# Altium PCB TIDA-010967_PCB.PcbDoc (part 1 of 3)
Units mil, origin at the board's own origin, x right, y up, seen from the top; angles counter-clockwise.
Board outline 2322.7 x 960 mil, 2 copper layers (Top Layer, Bottom Layer), stack 44.731 mil thick; 178 components, 80 nets, 496 pads, 399 vias.
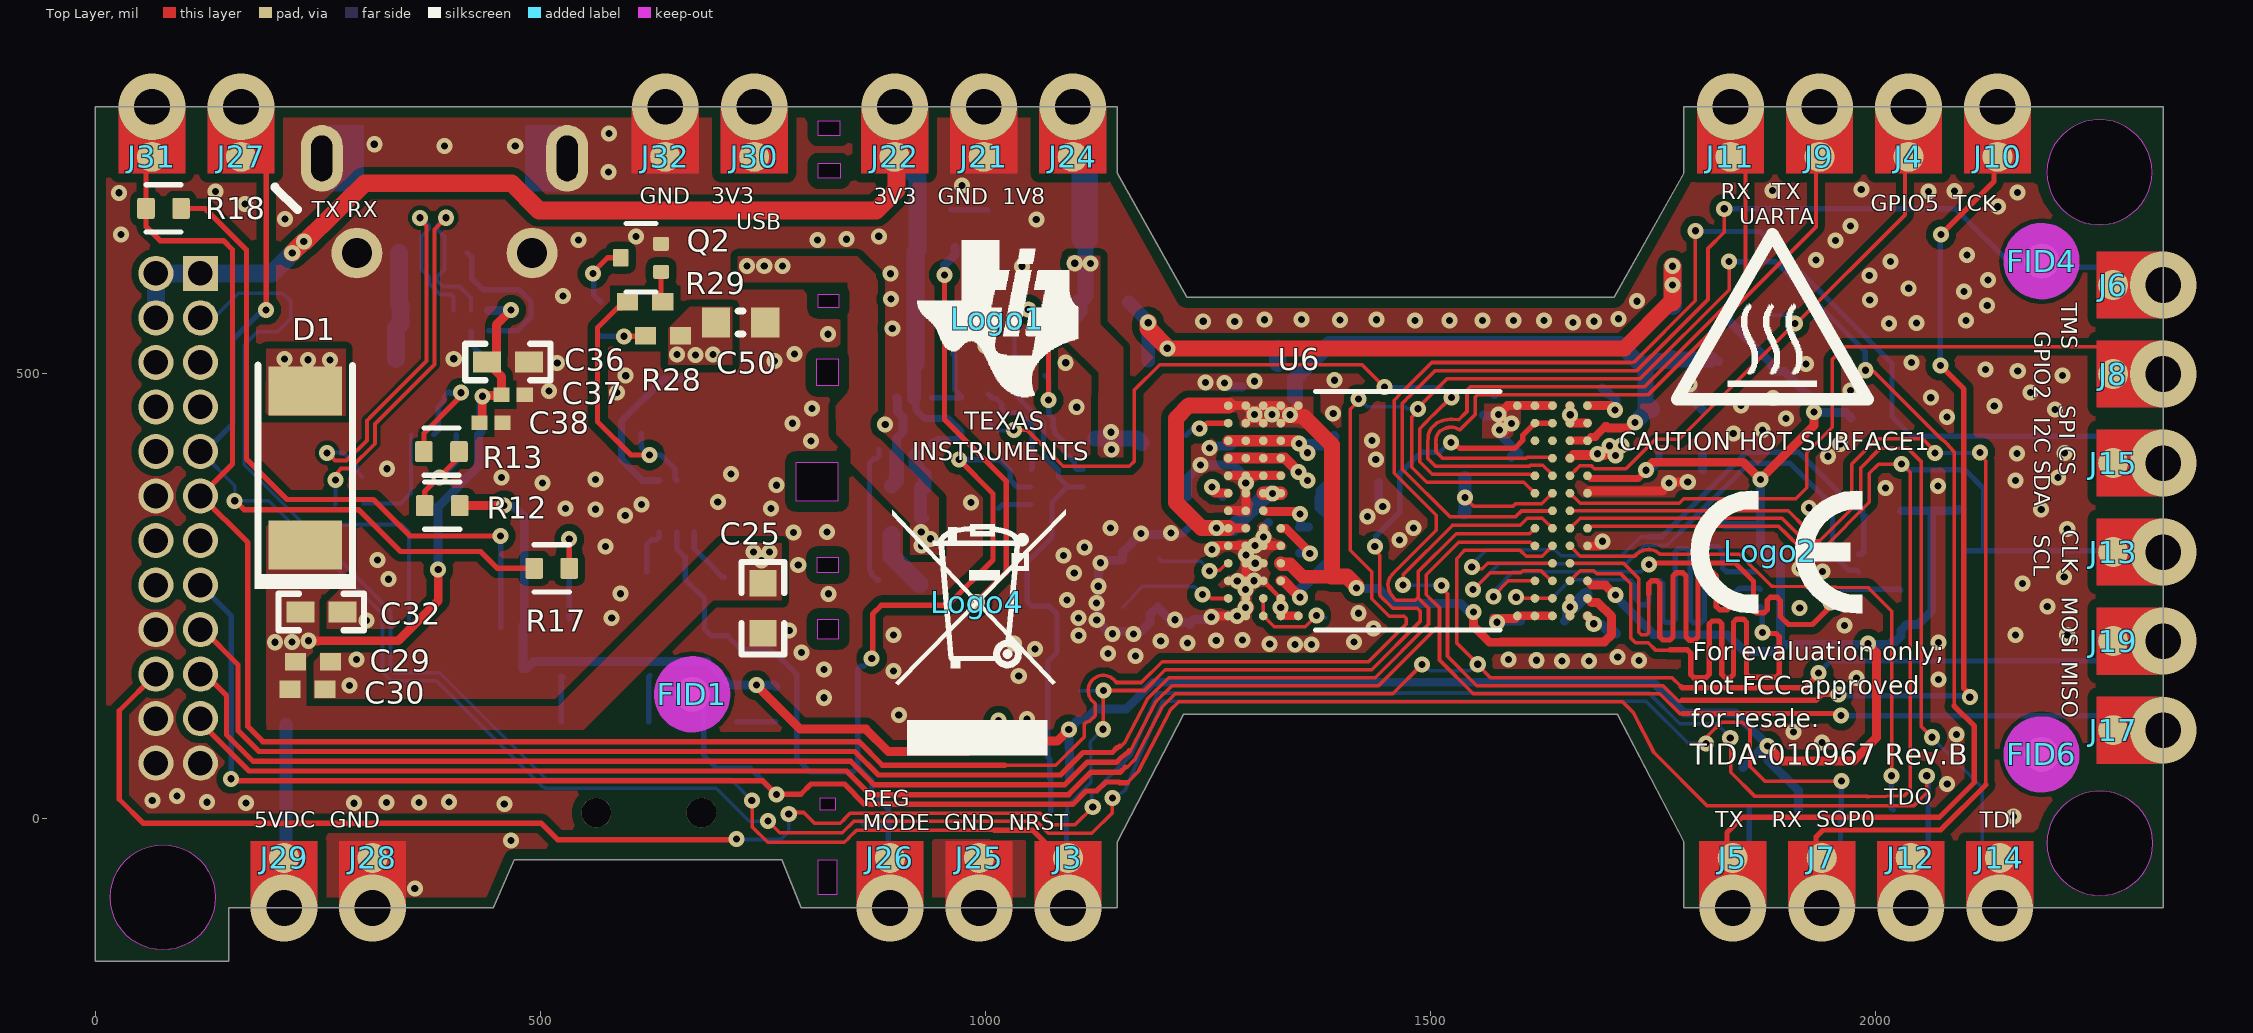
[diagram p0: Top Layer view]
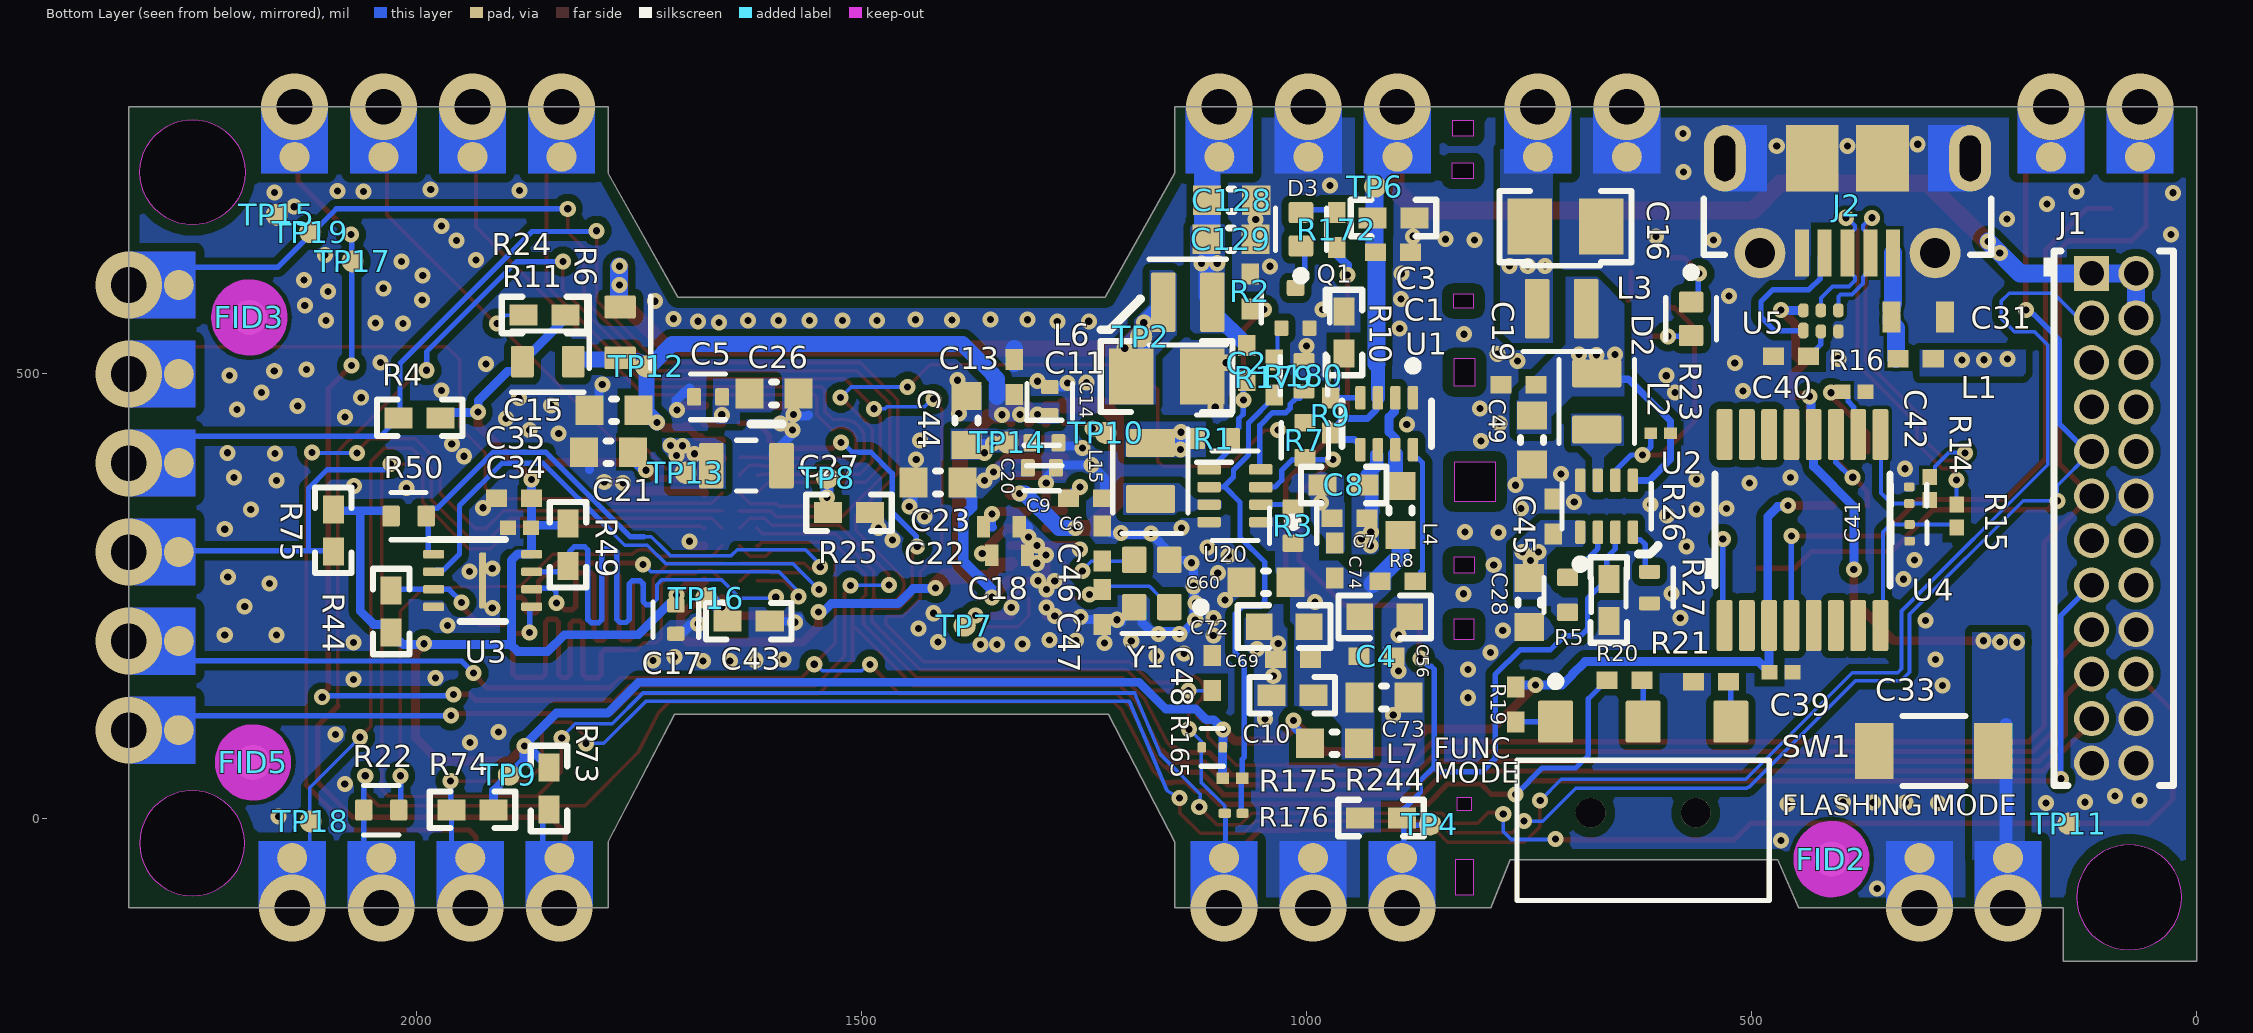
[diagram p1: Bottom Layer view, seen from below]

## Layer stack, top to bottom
Top Solder: solder mask 0.4, Solder Resist, Dk 4.5
Top Layer: signal copper 1.401
Dielectric 1: core 41.929, FR-4 High Tg135 (KB-6164), Dk 4.5
Bottom Layer: signal copper 1.401
Bottom Solder: solder mask 0.4, Solder Resist, Dk 4.5

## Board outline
150,-160 150,-100 447,-100 470.42,-45.84 470.38,-45.81 771.2,-45.81 770.94,-45.67 793,-100 1147.72,-100 1147.72,-25.77 1222.67,117.74 1709.51,117.74 1784.42,-25.77 1784.42,-100 2322.7,-100 2322.7,800 1784.42,800 1784.42,725.77 1705.96,586 1225.82,586 1147.73,725.77 1147.73,800 0,800 0,-160
cut-out: 2192.07,726.38 ccw(c2251.12,726.38) 2251.12,667.32 ccw(c2251.12,726.38) 2310.18,726.38 ccw(c2251.12,726.38) 2251.12,785.43 ccw(c2251.12,726.38)
cut-out: 75.87,-147.12 cw(c75.87,-88.07) 16.81,-88.07 cw(c75.87,-88.07) 75.87,-29.01 cw(c75.87,-88.07) 134.92,-88.07 cw(c75.87,-88.07)
cut-out: 2192.49,-27.28 cw(c2251.54,-27.28) 2251.54,31.77 cw(c2251.54,-27.28) 2310.6,-27.28 cw(c2251.54,-27.28) 2251.54,-86.34 cw(c2251.54,-27.28)
cut-out: 787.23,357.01 787.23,400.93 834.15,400.93 834.15,357.01
cut-out: 811.61,202.06 811.61,224.32 834.73,224.32 834.73,202.06
cut-out: 810.96,276.6 810.96,294.06 834.49,294.06 834.49,276.6
cut-out: 812.12,719.77 812.12,736.24 836.79,736.24 836.79,719.77
cut-out: 811.87,574.08 811.87,589.42 835.26,589.42 835.26,574.08
cut-out: 812.12,767.55 812.12,784.24 836.23,784.24 836.23,767.55
cut-out: 810.45,486.64 810.45,516.86 834.73,516.86 834.73,486.64
cut-out: 814.29,9.7 814.29,23.97 830.94,23.97 830.94,9.7
cut-out: 812.08,-85.22 812.08,-45.84 833,-45.84 833,-85.22

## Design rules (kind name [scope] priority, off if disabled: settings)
AcuteAngle [All] p1 off: minimum=4.50000000000000E+0001 checktracksonly=FALSE
AssemblyTestPointUsage [All] p1: valid=2
BoardOutlineClearance [All] p1: gap=12 ignorepadtopadclearanceinfootprint=FALSE
Clearance Clearance_Keepout [IsKeepOut] p1: gap=5 ignorepadtopadclearanceinfootprint=TRUE
Clearance "Clearance_TX and RX" [InNetClass('TX and RX')] p2: gap=8 ignorepadtopadclearanceinfootprint=FALSE except(0: Text-Hole; 4: Arc-Text Track-Text SMDPad-Text THPad-Text Via-Text Fill-Text Poly-Text Region-Text Text-Text; 5.3: Arc-Via Arc-Fill Arc-Poly Arc-Region Track-Via Track-Fill Track-Poly Track-Region Poly-Region; 6: Arc-Hole Track-Hole SMDPad-Via SMDPad-Hole THPad-Hole Via-Hole; 7.7: Fill-Fill Fill-Poly Fill-Region Poly-Poly Region-Region; 10: Arc-SMDPad Arc-THPad Track-SMDPad Track-THPad SMDPad-SMDPad SMDPad-THPad THPad-THPad THPad-Via; 11: Fill-Hole Poly-Hole Region-Hole)
Clearance Clearance_BGA [WithinRoom('BGA1')] p3: gap=4 ignorepadtopadclearanceinfootprint=FALSE except(8: Fill-Fill Fill-Poly Fill-Region Poly-Poly Poly-Region Region-Region; 10: Fill-Hole Poly-Hole Region-Hole)
Clearance Clearance_USB [WithinRoom('USB')] p4: gap=4 ignorepadtopadclearanceinfootprint=FALSE except(8: Fill-Fill Fill-Poly Fill-Region Poly-Poly Poly-Region Region-Region; 10: Fill-Hole Poly-Hole Region-Hole)
Clearance "top and bottom" [OnTopLayer or OnBottomLayer] p5: gap=6 ignorepadtopadclearanceinfootprint=TRUE except(5: Arc-Arc Arc-Track Arc-SMDPad Arc-Hole Track-Track Track-SMDPad Track-Hole SMDPad-Hole THPad-Hole Via-Hole Text-Hole; 5.1: SMDPad-SMDPad; 7: Arc-Fill Arc-Poly Arc-Region Track-Fill Track-Region; 8: Track-Poly SMDPad-Fill SMDPad-Poly SMDPad-Region THPad-Fill THPad-Poly THPad-Region Via-Fill Via-Poly Via-Region Poly-Poly; 10: Fill-Fill Fill-Poly Fill-Region Poly-Region Region-Region; 11: Fill-Hole Poly-Hole Region-Hole)
Clearance Clearance_KO-J5 [IsKeepOut and IsTrack vs InComponent('J5')] p6: gap=19.6 ignorepadtopadclearanceinfootprint=FALSE
Clearance [All] p7: gap=6 ignorepadtopadclearanceinfootprint=TRUE except(0: Text-Hole; 5: Arc-Arc Arc-Track Arc-SMDPad Track-Track Track-SMDPad; 5.1: SMDPad-SMDPad; 7: Arc-Fill Arc-Poly Arc-Region Track-Fill Track-Region; 8: SMDPad-Fill SMDPad-Poly SMDPad-Region THPad-Fill THPad-Poly THPad-Region; 10: Fill-Fill Fill-Poly Fill-Region Poly-Region Region-Region; 11: Fill-Hole Poly-Hole Region-Hole; 12: Track-Poly; 15: Poly-Poly)
Clearance Same_net [All] p8: gap=0 ignorepadtopadclearanceinfootprint=TRUE
ComponentClearance ComponentClearance_MatingCon-3D [All vs not InAnyComponent] p1: gap=0 collisioncheckmode=3 verticalgap=0 showdistances=FALSE
ComponentClearance "ComponentClearance_WEE Logo" [InComponent('Logo4')] p2: gap=0 collisioncheckmode=3 verticalgap=0 showdistances=TRUE
ComponentClearance ComponentClearance_R77 [InComponent('R77') vs InComponent('Logo1')] p3: gap=0 collisioncheckmode=3 verticalgap=0 showdistances=TRUE
ComponentClearance ComponentClearance_Logo [InComponentClass('Logo')] p4: gap=0 collisioncheckmode=3 verticalgap=0 showdistances=TRUE
ComponentClearance "ComponentClearance_Mounting Holes_Fiducial Marks" [InComponentClass('FiducialMark') vs InPadClass('Mounting Holes PADS')] p5: gap=50 collisioncheckmode=3 verticalgap=10 showdistances=TRUE
ComponentClearance [All] p6: gap=6 collisioncheckmode=3 verticalgap=10 showdistances=TRUE
DiffPairsRouting 90ohm [All] p1: maxlimit=4.5 minlimit=4.5 mostfreqgap=4.5 toplayer_minwidth=4.5 toplayer_maxwidth=4.5 toplayer_prefwidth=4.5 bottomlayer_minwidth=4.5 bottomlayer_maxwidth=4.5 bottomlayer_prefwidth=4.5 maxuncoupledlength=500
FabricationTestPointUsage TestPointUsage [All] p1: valid=2 allowmultiple=FALSE
FabricationTestpoint Testpoint [All] p1: side=3 testpointundercomponent=TRUE minsize=40 maxsize=100 preferedsize=60 minholesize=0 maxholesize=40 preferedholesize=32 testpointgrid=1 allowsidetop=TRUE allowsidebottom=TRUE usegrid=TRUE gridtolerance=0.01
FanoutControl Fanout_LCC [IsLCC] p1: bgadir=Out bgaviamode=Centered fanoutstyle=Auto fanoutdirection=Alternating viagrid=1 // Fanout_LCC (Default Rule)
FanoutControl Fanout_BGA [IsBGA] p2: bgadir=Out bgaviamode=Centered fanoutstyle=Auto fanoutdirection=Alternating viagrid=1 // Fanout_BGA (Default Rule)
FanoutControl Fanout_Default [All] p4: bgadir=Out bgaviamode=Centered fanoutstyle=Auto fanoutdirection=Alternating viagrid=1 // Fanout_Default (Default Rule)
FanoutControl Fanout_Small [(CompPinCount < 5)] p5: bgadir=Out bgaviamode=Centered fanoutstyle=Auto fanoutdirection=OutThenIn viagrid=1 // Fanout_Small (Default Rule)
Height Room_Hieght [WithinRoom('Room_Hieght 1 MM')] p1: minheight=0 maxheight=41.34 prefheight=39.37
HoleSize [All] p1: absolutevalues=TRUE maxlimit=280 minlimit=5.9 maxpercent=80.000 minpercent=20.000
HoleToHoleClearance HoleToHoleClearance_1 [WithinRoom('BGA1')] p1: gap=4 allowstackedmicrovias=FALSE
MatchedLengths MatchLengths_xSignals_U3_U6 [InxSignalClass('xSignals_U3_U6_MatchLengthsClass')] p1: tolerance=30 checknetsindiffpair=FALSE checkdiffpairvsdiffpair=TRUE checkxsignals=TRUE checkothers=TRUE
MatchedLengths MatchLengths_xSignals_U2_U1_1 [InxSignalClass('xSignals_U2_U1_MatchLengthsClass_1')] p2: tolerance=100 checknetsindiffpair=FALSE checkdiffpairvsdiffpair=TRUE checkxsignals=TRUE checkothers=TRUE
MatchedLengths MatchLengths_U2_Passives_U1 [InxSignalClass('xSignals_U2_Passives_U1_MatchLengthsClass')] p3: tolerance=100 checknetsindiffpair=FALSE checkdiffpairvsdiffpair=TRUE checkxsignals=TRUE checkothers=TRUE
MatchedLengths MatchLengths_xSignals_U2_Passives [InxSignalClass('xSignals_U2_Passives_MatchLengthsClass')] p4: tolerance=100 checknetsindiffpair=FALSE checkdiffpairvsdiffpair=TRUE checkxsignals=TRUE checkothers=TRUE
MatchedLengths MatchLengths_xSignals_U2_U1 [InxSignalClass('xSignals_U2_U1_MatchLengthsClass')] p5: tolerance=100 checknetsindiffpair=FALSE checkdiffpairvsdiffpair=TRUE checkxsignals=TRUE checkothers=TRUE
MatchedLengths [InxSignalClass('QPSI')] p6: tolerance=10 checknetsindiffpair=FALSE checkdiffpairvsdiffpair=TRUE checkxsignals=TRUE checkothers=TRUE
MinimumAnnularRing MinimumAnnularRing_ThermalPadVias [IsVia and InAnyComponent] p1: minimumring=3.9
MinimumAnnularRing [All] p2: minimumring=3.9
MinimumSolderMaskSliver MinimumSolderMaskSliver_Logo [InComponentClass('Logo') vs InComponentClass('Logo')] p1: minsoldermaskwidth=0.7
MinimumSolderMaskSliver [All] p2: minsoldermaskwidth=3.5
PlaneConnect [All] p1: planeconnectstyle=Relief reliefexpansion=10 reliefentries=4 reliefconductorwidth=10 reliefairgap=10
PolygonConnect [All] p1: connectstyle=Direct reliefconductorwidth=10 reliefentries=4 polygonreliefangle="90 Angle" airgapwidth=10
RoomDefinition BGA1 [InComponentClass('Components Class 2')] p1: confinementstyle=ConfineIn formatcopy=TRUE lockcomponents=FALSE outline 1572.65,427.73 1907.13,427.73 1907.13,252.98 1572.65,252.98
RoomDefinition USB [InComponentClass('Components Class 2')] p2: confinementstyle=ConfineIn formatcopy=TRUE lockcomponents=FALSE outline 252.62,689.5 405.92,689.5 405.92,368.59 252.62,368.59
RoutingVias ThermalPadVias [IsVia and InAnyComponent] p1: holewidth=7.87 width=19.68 viastyle="Through Hole" minholewidth=5 minwidth=13 maxholewidth=12.99 maxwidth=23.62
RoutingVias [All] p2: holewidth=12.2 width=22.4 viastyle="Through Hole" minholewidth=5.9 minwidth=14 maxholewidth=20 maxwidth=40
SMDToCorner [All] p1: distance=25000
SilkToBoardRegionClearance [Not ((IsComment or IsDesignator) And (Hide <> 'False')) and not InRegion(1000,500,4000,800)] p1:
SilkToSilkClearance [All] p1: silktosilkclearance=3
SilkToSolderMaskClearance SilkToSolderMaskClearance_OutLine [istrack and InAnyComponent] p1: minsilkscreentomaskgap=0 clearancetoexposedcopper=FALSE
SilkToSolderMaskClearance SilkscreenOverComponentPads [IsPad] p2: minsilkscreentomaskgap=3 clearancetoexposedcopper=FALSE
SolderMaskExpansion [All] p1: expansion=0 istentingtop=FALSE
SupplyNets "Schematic Supply Nets_18" [InNet('RADAR_1V_RF_OUT')] p1: voltage=0.000
SupplyNets "Schematic Supply Nets_17" [InNet('5V_IN_USB')] p2: voltage=0.000
SupplyNets "Schematic Supply Nets_16" [InNet('OUT_3V3')] p3: voltage=0.000
SupplyNets "Schematic Supply Nets_15" [InNet('REG_OUT_1V8')] p4: voltage=0.000
SupplyNets "Schematic Supply Nets_14" [InNet('REG_3V3')] p5: voltage=0.000
SupplyNets "Schematic Supply Nets_13" [InNet('RADAR_1V4_APLL')] p6: voltage=0.000
SupplyNets "Schematic Supply Nets_12" [InNet('RADAR_SRAM_1V2')] p7: voltage=0.000
SupplyNets "Schematic Supply Nets_11" [InNet('GND')] p8: voltage=0.000
SupplyNets "Schematic Supply Nets_10" [InNet('RADAR_1V2')] p9: voltage=0.000
SupplyNets "Schematic Supply Nets_9" [InNet('RADAR_1P2_RF')] p10: voltage=0.000
SupplyNets "Schematic Supply Nets_8" [InNet('RADAR_1V8')] p11: voltage=0.000
SupplyNets "Schematic Supply Nets_7" [InNet('RADAR_1V4_SYNTH')] p12: voltage=0.000
SupplyNets "Schematic Supply Nets_6" [InNet('USB_5V')] p13: voltage=0.000
SupplyNets "Schematic Supply Nets_5" [InNet('USB_INPUT_3V3')] p14: voltage=0.000
SupplyNets "Schematic Supply Nets_4" [InNet('RADAR_3V3')] p15: voltage=0.000
SupplyNets "Schematic Supply Nets_3" [InNet('REG_1V8')] p16: voltage=0.000
SupplyNets "Schematic Supply Nets_2" [InNet('VPP_1P7')] p17: voltage=0.000
SupplyNets "Schematic Supply Nets_1" [InNet('RADAR_VBGAP')] p18: voltage=0.000
SupplyNets "Schematic Supply Nets" [InNet('DC_OUT_3V3')] p19: voltage=0.000
UnRoutedNet [All] p1: checkbadconnections=TRUE
Width [All] p1: maxlimit=100 minlimit=4 preferedwidth=10 toplayer_prefwidth=6 minimp=50.000000 maximp=50.000000 favimp=50.000000
12 further rules are at their usual default settings.

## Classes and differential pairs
component class TIDA-010967_xWRL6432_Chip: C43 C46 C47 C48 R4 R22 R24 R25 R73 R74 R75 R165 TP7 TP8 TP10 TP12 TP13 TP14 TP15 TP16 TP17 TP18 TP19 U6 Y1
component class TIDA-010967_USB_PWR_Connector: C29 C30 C31 C32 C33 C36 C37 C38 C39 C40 C41 C42 D1 J1 J2 J3 J4 J5 J6 J7 J8 J9 J10 J11 J12 J13 J14 J15 J17 J19 J21 J22 J24 J25 J26 J27 J28 J29 J30 J31 J32 J? L1 R12 R13 R14 R15 R16 R17 R18 R19 R20 R21 SW1 U4 U5
component class TIDA-010967_QSPI_Flash: C34 C35 R44 R49 R50 U3
component class TIDA-010967_Decoupling_caps: C5 C6 C9 C13 C14 C15 C17 C18 C20 C21 C22 C23 C26 C27 C44 L7 R6 R11
component class TIDA-010967_DC_Regulators: C1 C2 C3 C4 C7 C8 C10 C11 C16 C19 C25 C28 C45 C49 C50 C56 C60 C69 C72 C73 C74 C128 C129 D2 D3 L2 L3 L4 L6 L15 Q1 Q2 R1 R2 R3 R5 R7 R8 R9 R10 R23 R26 R27 R28 R29 R172 R175 R176 R179 R180 R244 TP2 TP4 TP6 TP9 TP11 U1 U2 U20
net class POWER: PMIC_CLKOUT_SOP1 REG_1V8 REG_OUT_1V8
net class Regions: GND XTALP
component class Logo: Logo1
component class FiducialMark: FID1 FID2 FID3 FID4 FID5 FID6
component class TIDA-010967_Hardware: "CAUTION HOT SURFACE1" FID1 FID2 FID3 FID4 FID5 FID6 Logo1 Logo2 Logo4 ZZ1 ZZ2 ZZ3 ZZ4 ZZ5
component class AssemblyNote: ZZ1 ZZ2 ZZ3 ZZ4 ZZ5
component class Header: J1 LD2 LD4 SW2
differential pair USB_DifferentialPair1: +USB_DP -USB_DM
differential pair CAN: +"" -""
differential pair LVDS_FRCLK: +"" -""
differential pair LVDS_FRCLK_DP8: +"" -""
differential pair LVDS_CLK: +"" -""
differential pair LVDS_CLK_DP7: +"" -""
differential pair LVDS_3: +"" -""
differential pair LVDS_3_DP6: +"" -""
differential pair LVDS_2: +"" -""
differential pair LVDS_2_DP5: +"" -""
differential pair LVDS_1: +"" -""
differential pair LVDS_1_DP4: +"" -""
differential pair LVDS_0: +"" -""
differential pair LVDS_0_DP3: +"" -""
differential pair USB_DP1: +USBDP -USBDM

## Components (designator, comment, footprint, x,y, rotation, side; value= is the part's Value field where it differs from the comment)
C1 "GRT155C81A105KE01D" 0402L 902.62,636.34 r180 bottom value=1uF
C2 "GRM1555C1H100JA01D" 0402L 1066.97,512.13 r270 bottom value=10pF
C3 "GCM155R71H104KE02D" 0402 902.23,675.03 r180 bottom value=0.1uF
C4 "GRT155C81A105KE01D" 0402L 921.46,182.75 r180 bottom value=1uF
C5 "GRM155R61A225ME01D" FP-GRM155R61A225ME01D_0402-MFG 1672.07,474.04 r180 bottom value=2.2µF
C6 "C1005X7R1H473K050BB" 0402L 1247.52,360.04 r180 bottom value=0.047uF
C7 "GRT155C81A105KE01D" 0402L 951.51,337.76 r0 bottom value=1uF
C8 "GCM155R71H104KE02D" 0402 958.13,375.12 r180 bottom value=0.1uF
C9 "GRM155R61A225ME01D" FP-GRM155R61A225ME01D_0402-MFG 1297.18,394.28 r0 bottom value=2.2µF
C10 "GCM155R71H104KE02D" 0402 1015.77,138.92 r0 bottom value=0.1uF
C11 "GRM21BR61A476ME15L" 0805_HV 1156.96,496.95 r180 bottom value=47uF
C13 "GRM155R71C224KA12D" 0402L 1328.14,496.44 r90 bottom value=0.22uF
C14 "GRM155R61A225ME01D" FP-GRM155R61A225ME01D_0402-MFG 1288.21,469.2 r270 bottom value=2.2µF
C15 "GRM188Z71A106MA73D" 0603L 1777.87,459.12 r0 bottom value=10uF
C16 "GRM21BR61A476ME15L" 0805_HV 708.95,665.27 r180 bottom value=47uF
C17 "GRM155R61A225ME01D" FP-GRM155R61A225ME01D_0402-MFG 1708.25,223.76 r90 bottom value=2.2µF
C18 "GRM155R70J105KA12D" 0402S 1333.23,296.06 r180 bottom value=1uF
C19 "GRM1555C1H100JA01D" 0402L 761.79,487.87 r0 bottom value=10pF
C20 "GRM155R61A225ME01D" FP-GRM155R61A225ME01D_0402-MFG 1294.33,422.3 r0 bottom value=2.2µF
C21 "GRM188Z71A106MA73D" 0603L 1783.84,411.93 r0 bottom value=10uF
C22 "GRM155R70J105KA12D" 0402S 1342.73,328.1 r180 bottom value=1uF
C23 "GRM188Z71A106MA73D" 0603L 1414,377.89 r0 bottom value=10uF
C25 "GRM188Z71A106MA73D" 0603_HV 749.85,236.7 r270 top value=10uF
C26 "GRM188Z71A106MA73D" 0603L 1598.21,477.81 r180 bottom value=10uF
C27 "GCJ21BR71C475KA01L" FP-GCJ21BR71C475KA01L_0805-MFG 1628.97,396.86 r0 bottom value=4.7µF
C28 "GRM188R71C474KA88D" 0603L 749.79,243.27 r270 bottom value=0.47uF
C29 "GCM155R71C224KE02D" 0402L 244.49,176.81 r180 top value=0.22uF
C30 "GCM155C71A474KE36D" 0402L 238.1,145.91 r0 top value=0.47uF
C31 "GRT188R61A106KE13D" 0603S 312.8,563.93 r0 bottom value=10uF
C32 "GRM155R61A106ME11D" 0402 253.83,232.53 r180 top value=10uF
C33 "GRM31CR61A476KE15L" 1206_180 295.19,76.51 r0 bottom value=47uF
C34 "GRM033C71A104KE14D" 0201 1883.74,326.93 r180 bottom value=0.1uF
C35 "GRM155R70J105KA12D" 0402L 1890.11,359.96 r0 bottom value=1uF
C36 "0402ZD106MAT2A" 0402_080 463.4,513.17 r0 top value=10uF
C37 "GRM033R61C104KE84D" 0201_033 469.41,476.41 r0 top value=0.1uF
C38 "GRM033R70J103KA01D" 0201 444.44,444.93 r0 top value=0.01uF
C39 "GRM033R61C104KE84D" 0201_033 466.96,164.72 r180 bottom value=0.1uF
C40 "GRM033R61C104KE84D" 0201_033 384.79,479.89 r180 bottom value=0.1uF
C41 "GCM0335C1E220JA16D" FP-GCM0335C1E220JA16D_0201-MFG 322.55,321.38 r90 bottom value=22pF
C42 "GCM0335C1E220JA16D" FP-GCM0335C1E220JA16D_0201-MFG 322.97,363.59 r270 bottom value=22pF
C43 "C1005X7R1H104K050BE" 0402 1626.41,222.13 r180 bottom value=0.1uF
C44 "GRM188Z71A106MA73D" 0603L 1381.93,447.66 r90 bottom value=10uF
C45 "GRM1555C1H471JA01D" 0402L 722.49,339.81 r90 bottom value=470pF
C46 "GJM1555C1H4R7BB01D" 0402L 1229.42,309.15 r270 bottom value=4.7pF
C47 "GJM1555C1H4R7BB01D" 0402L 1229.56,237.9 r90 bottom value=4.7pF
C48 "CL05B224KO5NNNC" 0402L 1105.76,163.78 r270 bottom value=0.22uF
C49 "GRM188Z71A106MA73D" 0603L 746.45,425.59 r270 bottom value=10uF
C50 "GRM188Z71A106MA73D" 0603L 724.93,557.48 r0 top value=10uF
C56 "GRM188Z71A106MA73D" 0603_HV 911.95,227 r180 bottom value=10uF
C60 "GRM188R71C474KA88D" 0603L 1045.37,265.79 r0 bottom value=0.47uF
C69 "GRM1555C1H471JA01D" 0402L 1015.01,179.1 r0 bottom value=470pF
C72 "GRM188Z71A106MA73D" 0603_HV 1025.05,215.91 r0 bottom value=10uF
C73 "GRM188R71C474KA88D" 0603L 912.93,136.47 r180 bottom value=0.47uF
C74 "GRM1555C1H471JA01D" 0402L 968.4,290.29 r90 bottom value=470pF
C128 "GRM188Z71A106MA73D" 0603L 1083.88,695.03 r180 bottom value=10uF
C129 "GRM188Z71A106MA73D" 0603L 1084.82,651.17 r180 bottom value=10uF
"CAUTION HOT SURFACE1" "CAUTION HOT SURFACE" IEC_HotSurface_Small 1883.74,564.43 r0 top
D1 "PMEG3020EP,115" SOD-128 235.78,394.13 r90 top value=30V
D2 "VLMY1500-GS08" FP-VLMY1500-GS08_0402-MFG 567.93,561.74 r270 bottom
D3 "VLMY1500-GS08" FP-VLMY1500-GS08_0402-MFG 1006.08,662.34 r90 bottom
FID1 "Fiducial" Fiducial10-20 670.53,139.97 r0 top
FID2 "Fiducial" Fiducial10-20 410.19,-45.15 r90 bottom
FID3 "Fiducial" Fiducial10-20 2187.29,563.32 r90 bottom
FID4 "Fiducial" Fiducial10-20 2186.11,626.55 r0 top
FID5 "Fiducial" Fiducial10-20 2183.2,63.48 r90 bottom
FID6 "Fiducial" Fiducial10-20 2186.07,72.45 r0 top
J1 "GRPB122VWVN-RC" Sullins_GRPB122VWVN 93.1,337.73 r180 bottom
J2 "105017-0001" CONN_105017-0001 392.23,688.84 r0 bottom
J3 "Castellation 2.54mm" "FP-Castellation 2.54mm_75mills" 1092.59,-100 r90 top
J4 "Castellation 2.54mm" "FP-Castellation 2.54mm_75mills" 2036.65,800 r270 top
J5 "Castellation 2.54mm" "FP-Castellation 2.54mm_75mills" 1839.17,-100 r90 top
J6 "Castellation 2.54mm" "FP-Castellation 2.54mm_75mills" 2322.82,599.73 r180 top
J7 "Castellation 2.54mm" "FP-Castellation 2.54mm_75mills" 1939.17,-100 r90 top
J8 "Castellation 2.54mm" "FP-Castellation 2.54mm_75mills" 2322.82,499.73 r180 top
J9 "Castellation 2.54mm" "FP-Castellation 2.54mm_75mills" 1936.65,800 r270 top
J10 "Castellation 2.54mm" "FP-Castellation 2.54mm_75mills" 2136.65,800 r270 top
J11 "Castellation 2.54mm" "FP-Castellation 2.54mm_75mills" 1836.65,800 r270 top
J12 "Castellation 2.54mm" "FP-Castellation 2.54mm_75mills" 2039.17,-100 r90 top
J13 "Castellation 2.54mm" "FP-Castellation 2.54mm_75mills" 2322.82,299.73 r180 top
J14 "Castellation 2.54mm" "FP-Castellation 2.54mm_75mills" 2139.17,-100 r90 top
J15 "Castellation 2.54mm" "FP-Castellation 2.54mm_75mills" 2322.82,399.73 r180 top
J17 "Castellation 2.54mm" "FP-Castellation 2.54mm_75mills" 2322.82,99.73 r180 top
J19 "Castellation 2.54mm" "FP-Castellation 2.54mm_75mills" 2322.82,199.73 r180 top
J21 "Castellation 2.54mm" "FP-Castellation 2.54mm_75mills" 997.82,800 r270 top
J22 "Castellation 2.54mm" "FP-Castellation 2.54mm_75mills" 897.82,800 r270 top
J24 "Castellation 2.54mm" "FP-Castellation 2.54mm_75mills" 1097.82,800 r270 top
J25 "Castellation 2.54mm" "FP-Castellation 2.54mm_75mills" 992.59,-100 r90 top
J26 "Castellation 2.54mm" "FP-Castellation 2.54mm_75mills" 892.59,-100 r90 top
J27 "Castellation 2.54mm" "FP-Castellation 2.54mm_75mills" 163.65,800 r270 top
J28 "Castellation 2.54mm" "FP-Castellation 2.54mm_75mills" 311.39,-100 r90 top
J29 "Castellation 2.54mm" "FP-Castellation 2.54mm_75mills" 212.04,-100 r90 top
J30 "Castellation 2.54mm" "FP-Castellation 2.54mm_75mills" 740.07,800 r270 top
J31 "Castellation 2.54mm" "FP-Castellation 2.54mm_75mills" 63.65,800 r270 top
J32 "Castellation 2.54mm" "FP-Castellation 2.54mm_75mills" 640.07,800 r270 top
L1 "BLM15PD300SZ1D" 0402L 315.56,516.74 r180 bottom
L2 "DFE201210U-R47M=P2" "FP-DFE201210U-R47M=P2_0805 (2012)-MFG" 673.87,468.87 r90 bottom value=0.47uH
L3 "SPH201610UR10MT" FP-SPH201610UR10MT_SMT_IND_2MM0_1MM6-MFG 713.35,573.15 r0 bottom value=0.1uH
L4 "BLM18KG121TH1D" 0603L 894.26,346.55 r270 bottom value="120 ohm"
L6 "SPH201610UR10MT" FP-SPH201610UR10MT_SMT_IND_2MM0_1MM6-MFG 1133.1,580.52 r0 bottom value=0.1uH
L7 "BLM18KG121TH1D" 0603L 968.27,84.96 r0 bottom value="120 ohm"
L15 "DFE201210U-R47M=P2" "FP-DFE201210U-R47M=P2_0805 (2012)-MFG" 1175.21,390.77 r90 bottom value=0.47uH
Logo1 "Texas Instruments" TI_Symbol_Overlay_Small 1013.33,561.7 r0 top
Logo2 "CE Mark" CE_Mark_3MM5 1881.62,300.64 r0 top
Logo4 "WEEE logo" WEEE_Minimum 990.53,243.57 r0 top
Q1 "SSM3K35AMFV,L3F" FP-SSM3K35AMFV,L3F_SOT-723-MFG 1012.23,573.86 r90 bottom
Q2 "SSM3K35AMFV,L3F" FP-SSM3K35AMFV,L3F_SOT-723-MFG 612.78,630.31 r180 top
R1 "RC0402JR-070RP" FP-RC0402JR-070RP_0402-MFG 1103.88,427.13 r0 bottom value=0
R2 "CRCW040240K2FKED" 0402L 1063.07,592.57 r270 bottom value=40.2k
R3 "RC0402JR-070RP" FP-RC0402JR-070RP_0402-MFG 1014.95,329.41 r270 bottom value=0
R4 "CRCW04022M00FKED" 0402 1995.98,450.51 r0 bottom value=2.00Meg
R5 "RC0402JR-070RP" FP-RC0402JR-070RP_0402-MFG 706.5,251.64 r270 bottom value=0
R6 "ERJ-3GEY0R00V" FP-ERJ-3GEY0R00V_0603-MFG 1770.96,546.48 r270 bottom
R7 "RC0402JR-070RP" FP-RC0402JR-070RP_0402-MFG 1001.68,425.43 r270 bottom value=0
R8 "CRCW040210K0FKED" 0402L 897.4,267.2 r180 bottom value=10.0k
R9 "CRCW040210K0FKED" 0402L 972.45,453.33 r270 bottom value=10.0k
R10 "CRCW0402100KFKED" 0402 957.75,546.48 r270 bottom value=100k
R11 "ERJ-3GEY0R00V" FP-ERJ-3GEY0R00V_0603-MFG 1852.06,513.68 r0 bottom
R12 "RC0402JR-070RP" FP-RC0402JR-070RP_0402-MFG 389.62,351.84 r180 top value=0
R13 "RC0402JR-070RP" FP-RC0402JR-070RP_0402-MFG 388.81,412.51 r0 top value=0
R14 "RC0201JR-0727RL" 0201 299.76,371.19 r270 bottom value=27
R15 "RC0201JR-0727RL" 0201 269.37,340.38 r270 bottom value=27
R16 "CRCW040210K0FKED" 0402L 455.47,519.53 r180 bottom value=10.0k
R17 "RC0402JR-070RP" FP-RC0402JR-070RP_0402-MFG 512.6,281.48 r0 top value=0
R18 "RC0402JR-070RP" FP-RC0402JR-070RP_0402-MFG 76.59,685.75 r0 top value=0
R19 "CRCW04027K87FKED" 0402L 764.63,128.76 r90 bottom value=7.87k
R20 "CRCW040210K0FKED" 0402L 642.55,155.99 r180 bottom value=10.0k
R21 "CRCW040282K5FKED" 0402L 545.5,153.87 r180 bottom value=82.5k
R22 "RT0402FRE0733R2L" FP-RT0402FRE0733R2L_0402-MFG 2039.17,9.95 r180 bottom value=33.2
R23 "CRCW0201100KFKED" 0201L 602.08,433.23 r0 bottom value=100k
R24 "CRCW04022M00FKED" 0402 1855.77,565.99 r0 bottom value=2.00Meg
R25 "CRCW04022M00FKED" 0402 1513.76,344 r180 bottom value=2.00Meg
R26 "RC0402FR-071ML" 0402 660.24,245.89 r270 bottom value=1.00Meg
R27 "CRCW040218K0FKEDC" FP-CRCW040218K0FKEDC_0402-MFG 614.57,259.9 r270 bottom value=18k
R28 "ERJ-2RKF5100X" 0402L 637.55,542.92 r180 top value=510
R29 "ERJ-2RKF5100X" 0402L 617.66,581.19 r180 top value=510
R44 "CRCW04022M00FKED" 0402 2028.01,232.97 r270 bottom value=2.00Meg
R49 "CRCW04022M00FKED" 0402 1829.52,307.97 r90 bottom value=2.00Meg
R50 "AC0402FR-0747K5L" FP-AC0402FR-0747K5L_0402-MFG 2008.47,340.16 r180 bottom value=47.5k
R73 "CRCW04022M00FKED" 0402 1850.85,34.28 r270 bottom value=2.00Meg
R74 "CRCW04022M00FKED" 0402 1936.65,10.2 r0 bottom value=2.00Meg
R75 "CRCW04022M00FKED" 0402 2092.97,324.18 r270 bottom value=2.00Meg
R165 "ERJ-1RHD1002C" FP-ERJ-1RHD1002C_0201-MFG 1105.76,80.38 r180 bottom value=10k
R172 "ERJ-2RKF5100X" 0402L 965.67,661.65 r90 bottom value=510
R175 "CRCW0201100KFKED" 0201L 1083.14,45.81 r180 bottom value=100k
R176 "RC0201JR-070RL" "FP-RC0201JR-070RL_0201 (0603 Metric)-IPC_C" 1081.76,6.3 r180 bottom
R179 "ERJ-2RKF5100X" 0402L 1036.12,495.93 r270 bottom value=510
R180 "CRCW040218K0FKEDC" FP-CRCW040218K0FKEDC_0402-MFG 1002.72,497.77 r90 bottom value=18k
R244 "RC0402FR-071ML" 0402 916.21,1.12 r0 bottom value=1.00Meg
SW1 "AYZ0102AGRLC" FP-AYZ0102AGRLC_SMT_SW_7MM2_5MM3-MFG 621.72,-12.81 r180 bottom
TP2 "TESTPOINT" TP_25MIL-SMT#1 1185.64,541.84 r90 top
TP4 "TESTPOINT" TP_25MIL-SMT#1 860.96,-6.11 r90 top
TP6 "TESTPOINT" TP_25MIL-SMT#2 922.72,710.33 r90 bottom
TP7 "TESTPOINT" TP_25MIL-SMT#2 1383.88,217.19 r90 bottom
TP8 "TESTPOINT" TP_25MIL-SMT#2 1538.18,383.04 r90 bottom
TP9 "TESTPOINT" TP_25MIL-SMT#1 1895.73,49.69 r90 top
TP10 "TESTPOINT" TP_25MIL-SMT#2 1225.4,433.56 r90 bottom
TP11 "TESTPOINT" TP_25MIL-SMT#1 143.85,-5.2 r90 top
TP12 "TESTPOINT" TP_25MIL-SMT#1 1741.78,508.42 r90 top
TP13 "TESTPOINT" TP_25MIL-SMT#2 1697.18,388.88 r90 bottom
TP14 "TESTPOINT" TP_25MIL-SMT#2 1335.56,422.85 r90 bottom
TP15 "TESTPOINT" TP_25MIL-SMT#2 2156.33,678.48 r90 bottom
TP16 "TESTPOINT" TP_25MIL-SMT#2 1673.88,247.98 r90 bottom
TP17 "TESTPOINT" TP_25MIL-SMT#1 2071.22,626.31 r90 top
TP18 "TESTPOINT" TP_25MIL-SMT#1 2118.21,-2.86 r90 top
TP19 "TESTPOINT" TP_25MIL-SMT#2 2119.04,659.24 r90 bottom
U1 "TPS2116DRLR" DRL0008A-MFG 909.82,443.88 r270 bottom
U2 "TPS6285021HQDRLRQ1" DRL0008A-MFG 662.79,351.17 r90 bottom
U3 "MX25R1635FZUIH0" USON-8L 1925.28,267.79 r180 bottom
U4 "FT230XS-R" SSOP-16 442.74,324.44 r90 bottom
U5 "TPD4E004DRYR" DRY0006A 422.12,559.47 r90 bottom
U6 "XI6432BRQAAMY" AMY0101A-MFG 1474.3,346.12 r180 top
U20 "TPS6285020MDRLR" DRL0008A-MFG 1080.17,362.99 r0 bottom
Y1 "XRCGB40M000F1S2GR0" FP-XRCGB40M000F1S2GR0_SMT_CRYSTAL_2MM0_1MM6-MFG 1173.63,264.5 r90 bottom
ZZ1 "This Assembly Note is for PCB labels only" AssemblyNoteLabel -1702.57,3094.58 r0 top
ZZ2 "These assemblies are ESD sensitive, ESD precautions shall be observed." AssemblyNote -1700.16,3016.6 r0 top
ZZ3 "These assemblies must be clean and free from flux and all contaminants. Use of no clean flux is not acceptable." AssemblyNote -1700.16,2929.79 r0 top
ZZ4 "These assemblies must comply with workmanship standards IPC-A-610 Class 2, unless otherwise specified." AssemblyNote -1679.59,2861.06 r0 top
ZZ5 "These assemblies must comply with workmanship standards IPC-A-610 Class 2, unless otherwise specified." AssemblyNote -1678.2,2773.47 r0 top

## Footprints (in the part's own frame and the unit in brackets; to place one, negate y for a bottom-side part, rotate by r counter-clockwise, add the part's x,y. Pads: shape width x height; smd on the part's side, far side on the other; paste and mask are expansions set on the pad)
0201 [mm] "Data from Kemet datasheet CC101_COM dated 7/28/11"
  rect 0.46x0.42 smd mask+0.048: 1(-0.33,0) 2(0.33,0)
  body extent -0.31,-0.16 0.31,0.16, height 0.26
0201_033 [mm] "SMD, 2-Leads, Height 0.33mm"
  rect 0.46x0.42 smd mask+0.048: 1(-0.33,0) 2(0.33,0)
  body extent -0.31,-0.16 0.31,0.16, height 0.33
0201L [mm] "Data from Kemet datasheet CC101_COM dated 7/28/11"
  rect 0.36x0.32 smd mask+0.048: 1(-0.28,0) 2(0.28,0)
  body extent -0.31,-0.16 0.31,0.16, height 0.26
0402 [mm] "0402 from SM-752 data"
  rect 0.8x0.6 smd: 1(-0.6,0) 2(0.6,0)
  silkscreen extent -1.22,-0.52 1.22,0.52, body extent -0.55,-0.3 0.55,0.3, height 0.6
0402_080 [mm] "SMD, 2-Leads, Body 1x0.5mm"
  rect 0.8x0.6 smd: 1(-0.6,0) 2(0.6,0)
  silkscreen extent -1.22,-0.52 1.22,0.52, body extent -0.65,-0.4 0.65,0.4, height 0.8
0402L [mm] "0402 from SM-752 data"
  rect 0.6x0.5 smd: 1(-0.5,0) 2(0.5,0)
  body extent -0.55,-0.3 0.55,0.3, height 0.6
0402S [mil] "Based on C0402S footprint from PADS legacy"
  rect 15x24 smd: 1(-20,0) 2(20,0)
  body extent -22,-12 22,12, height 24
0603_HV [mil] "Ernesto recommended land pattern.  26 mil between pads."
  rect 30x30 smd: 1(-28,0) 2(28,0)
  silkscreen extent -52,-24 52,24, body extent -34,-19 34,19, height 39
0603L [mm] "0603 from SM-752 data"
  rect 0.8x0.85 smd: 1(-0.7,0) 2(0.7,0)
  silkscreen extent -0.07,-0.33 0.07,0.33, body extent -0.87,-0.47 0.87,0.47, height 1
0603S [mil]
  rect 20x35 smd: 1(-30,0) 2(30,0)
  body extent -34,-19 34,19, height 39
0805_HV [mil] "0805 with 30mil clearance between pads"
  rect 50x63 smd: 1(-40,0) 2(40,0)
  silkscreen extent -74,-40 74,40, body extent -43,-29 43,29, height 57
1206_180 [mm] "1206_180"
  rect 1.1x1.6 smd: 1(-1.7,0) 2(1.7,0)
  silkscreen extent -0.9,-1 0.9,1, body extent -1.75,-0.95 1.75,0.95, height 1.8
AMY0101A-MFG [mm]
  round 0.25 smd paste+0 mask+0.05: A1(-5.125,3) A2(-4.625,3) A3(-4.125,3) A4(-3.625,3) A5(-3.125,3) A6(3.125,3) A7(3.625,3) A8(4.125,3) A9(4.625,3) A10(5.125,3) B1(-5.125,2.5) B2(-4.625,2.5) B3(-4.125,2.5) B4(-3.625,2.5) B7(3.625,2.5) B8(4.125,2.5) B9(4.625,2.5) B10(5.125,2.5) C1(-5.125,2) C2(-4.625,2) C3(-4.125,2) C4(-3.625,2) C7(3.625,2) C8(4.125,2) C9(4.625,2) C10(5.125,2) D2(-4.625,1.5) D3(-4.125,1.5) D7(3.625,1.5) D8(4.125,1.5) D9(4.625,1.5) D10(5.125,1.5) E1(-5.125,1) E2(-4.625,1) E3(-4.125,1) E4(-3.625,1) E7(3.625,1) E8(4.125,1) E9(4.625,1) E10(5.125,1) F1(-5.125,0.5) F2(-4.625,0.5) F3(-4.125,0.5) F4(-3.625,0.5) F7(3.625,0.5) F8(4.125,0.5) F9(4.625,0.5) F10(5.125,0.5) G2(-4.625,0) G3(-4.125,0) G8(4.125,0) G9(4.625,0) G10(5.125,0) H1(-5.125,-0.5) H2(-4.625,-0.5) H3(-4.125,-0.5) H4(-3.625,-0.5) H7(3.625,-0.5) H8(4.125,-0.5) H9(4.625,-0.5) H10(5.125,-0.5) J1(-5.125,-1) J2(-4.625,-1) J3(-4.125,-1) J4(-3.625,-1) J7(3.625,-1) J8(4.125,-1) J9(4.625,-1) J10(5.125,-1) K2(-4.625,-1.5) K3(-4.125,-1.5) K7(3.625,-1.5) K8(4.125,-1.5) K9(4.625,-1.5) K10(5.125,-1.5) L1(-5.125,-2) L2(-4.625,-2) L3(-4.125,-2) L4(-3.625,-2) L7(3.625,-2) L8(4.125,-2) L9(4.625,-2) L10(5.125,-2) M1(-5.125,-2.5) M2(-4.625,-2.5) M3(-4.125,-2.5) M4(-3.625,-2.5) M7(3.625,-2.5) M8(4.125,-2.5) M9(4.625,-2.5) M10(5.125,-2.5) N1(-5.125,-3) N2(-4.625,-3) N3(-4.125,-3) N4(-3.625,-3) N5(-3.125,-3) N6(3.125,-3) N7(3.625,-3) N8(4.125,-3) N9(4.625,-3) N10(5.125,-3)
  silkscreen extent -2.63,-3.4 2.63,3.4, body extent -6,-3.9 6,3.9, height 0.25
AssemblyNote [mil] "Assembly Note"
AssemblyNoteLabel [mil] "Assembly Note for PCB Labels"
CE_Mark_3MM5 [mil]
  silkscreen extent -90,-70 103,68
CONN_105017-0001 [mm] "Molex Micro USB-B"
  rect 0.4x1.35 smd: 1(-1.3,1.35) 2(-0.65,1.35) 3(0,1.35) 4(0.65,1.35) 5(1.3,1.35)
  oval 1.2x1.9 hole 0.6 slot 1.3 at 90 deg: 6(-3.5,-1.35) 9(3.5,-1.35)
  rect 1.5x1.9 smd: 7(-1,-1.35) 8(1,-1.35)
  round 1.45 hole 0.85: 10(2.5,1.35) 11(-2.5,1.35)
  Top Layer region: 3.5,-2.3 2.3,-2.3 2.3,-0.4 3.5,-0.4
  Top Layer region: -3.5,-0.4 -2.3,-0.4 -2.3,-2.3 -3.5,-2.3
  silkscreen extent -4.1,-0.2 4.1,1.4, body extent -4.1,-3.93 4.1,1.5, height 2.72
DRL0008A-MFG [mm]
  rrect33% 0.67x0.3 smd paste+0 mask+0: 1(-0.74,0.75) 2(-0.74,0.25) 3(-0.74,-0.25) 4(-0.74,-0.75) 5(0.74,-0.75) 6(0.74,-0.25) 7(0.74,0.25) 8(0.74,0.75)
  silkscreen extent -1.77,-1.28 0.65,1.28, body extent -0.8,-1.05 0.8,1.05, height 0.6
DRY0006A [mm] "USON-6"
  rrect67% 0.45x0.3 smd paste-0.05 mask-0.05: 1(-0.275,0.5)
  rrect67% 0.4x0.3 smd paste-0.05 mask-0.05: 2(-0.3,0) 3(-0.3,-0.5) 4(0.3,-0.5) 5(0.3,0) 6(0.3,0.5)
  body extent -0.5,-0.72 0.5,0.72, height 0.58
Fiducial10-20 [mm]
  round 1 smd mask+0.5: 1(0,0)
  Top Layer keep-out circle w1.178: c0,0 r0.5
FP-AC0402FR-0747K5L_0402-MFG [mm]
  rrect20% 0.5x0.6 smd paste+0 mask+0: 1(-0.5,0) 2(0.5,0)
  silkscreen extent -0.5,-0.67 0.5,0.67, body extent -0.5,-0.25 0.5,0.25, height 0.37
FP-AYZ0102AGRLC_SMT_SW_7MM2_5MM3-MFG [mm]
  rrect10% 1x1.2 smd paste+0 mask+0: 1(-2.5,3.1) 2(0,3.1) 3(2.5,3.1)
  round 0.85 hole 0.85 unplated paste-2539.97 mask+0: ""(-1.5,0.5) ""(1.5,0.5)
  silkscreen extent -3.6,-2 3.6,4.37, body extent -3.6,-2 3.6,3.3, height 1.5
"FP-Castellation 2.54mm_75mills" [mil]
  round 33.75 smd far side paste-39370.1 mask+0: 1(56.25,0)
  round 33.75 smd paste-39370.1 mask+0: 1(56.25,0)
  Top Layer region: 75,37.5 0,37.5 16.27,33.79 29.32,23.38 36.56,8.34 36.56,-8.34 29.32,-23.38 16.27,-33.79 0,-37.5 0,-37.5 75,-37.5
  Bottom Layer region: 75,37.5 0,37.5 16.27,33.79 29.32,23.38 36.56,8.34 36.56,-8.34 29.32,-23.38 16.27,-33.79 0,-37.5 0,-37.5 75,-37.5
FP-CRCW040218K0FKEDC_0402-MFG [mm]
  rrect25% 0.4x0.6 smd paste+0 mask+0: 1(-0.45,0) 2(0.45,0)
  silkscreen extent -0.55,-0.67 0.55,0.67, body extent -0.5,-0.25 0.5,0.25, height 0.35
"FP-DFE201210U-R47M=P2_0805 (2012)-MFG" [mm]
  rrect13% 0.8x1.4 smd paste+0 mask+0: 1(-0.8,0) 2(0.8,0)
  silkscreen extent -1.2,-1.07 1.2,1.07, body extent -1,-0.6 1,0.6, height 1
FP-ERJ-1RHD1002C_0201-MFG [mm]
  rrect40% 0.25x0.3 smd paste+0 mask+0: 1(-0.3,0) 2(0.3,0)
  silkscreen extent -0.32,-0.54 0.32,0.54, body extent -0.3,-0.15 0.3,0.15, height 0.26
FP-ERJ-3GEY0R00V_0603-MFG [mm]
  rrect15% 0.65x0.9 smd paste+0 mask+0: 1(-0.725,0) 2(0.725,0)
  silkscreen extent -1.03,-0.87 1.03,0.87, body extent -0.8,-0.4 0.8,0.4, height 0.55
FP-GCJ21BR71C475KA01L_0805-MFG [mm]
  rrect14% 0.7x1.3 smd paste+0 mask+0: 1(-1,0) 2(1,0)
  silkscreen extent -0.28,-0.72 0.28,0.72, body extent -1,-0.63 1,0.63, height 1.45
FP-GCM0335C1E220JA16D_0201-MFG [mm] "Recommended Land Pattern"
  rrect40% 0.25x0.3 smd paste+0 mask+0: 1(-0.238,0) 2(0.238,0)
  silkscreen extent -0.3,-0.5 0.3,0.5, body extent -0.3,-0.15 0.3,0.15, height 0.33
FP-GRM155R61A225ME01D_0402-MFG [mm]
  rrect25% 0.4x0.5 smd paste+0 mask+0: 1(-0.4,0) 2(0.4,0)
  silkscreen extent -0.5,-0.65 0.5,0.65, body extent -0.5,-0.25 0.5,0.25, height 0.55
"FP-RC0201JR-070RL_0201 (0603 Metric)-IPC_C" [mil]
  rrect38% 13.94x10.34 smd paste+0 mask+0: 1(-10.01,0) 2(10.01,0)
  body extent -12,-6 12,6, height 10
FP-RC0402JR-070RP_0402-MFG [mm]
  rrect20% 0.5x0.6 smd paste+0 mask+0: 1(-0.5,0) 2(0.5,0)
  silkscreen extent -0.5,-0.67 0.5,0.67, body extent -0.5,-0.25 0.5,0.25, height 0.4
FP-RT0402FRE0733R2L_0402-MFG [mm]
  rrect20% 0.5x0.6 smd paste+0 mask+0: 1(-0.5,0) 2(0.5,0)
  silkscreen extent -0.5,-0.71 0.5,0.7, body extent -0.5,-0.25 0.5,0.25, height 0.35
FP-SPH201610UR10MT_SMT_IND_2MM0_1MM6-MFG [mm] "Recommended Land Pattern"
  rrect14% 0.7x1.7 smd paste+0 mask+0: 1(-0.7,0) 2(0.7,0)
  silkscreen extent -1.1,-1.22 1.1,1.22, body extent -1,-0.8 1,0.8, height 1
FP-SSM3K35AMFV,L3F_SOT-723-MFG [mm]
  rrect25% 0.45x0.4 smd paste+0 mask+0: 1(-0.575,0.4) 2(-0.575,-0.4)
  rrect22% 0.45x0.5 smd paste+0 mask+0: 3(0.575,0)
  silkscreen extent -0.43,-0.97 0.43,0.97, body extent -0.6,-0.6 0.6,0.6, height 0.55
FP-VLMY1500-GS08_0402-MFG [mm]
  rrect17% 0.6x0.7 smd paste+0 mask+0: 1(-0.475,0) 2(0.475,0)
  silkscreen extent -1.45,-0.72 0.6,0.72, body extent -0.5,-0.25 0.5,0.25, height 0.35
FP-XRCGB40M000F1S2GR0_SMT_CRYSTAL_2MM0_1MM6-MFG [mm]
  rrect14% 0.75x0.7 smd paste+0 mask+0: 1(-0.675,-0.5) 2(0.675,-0.5) 3(0.675,0.5) 4(-0.675,0.5)
  silkscreen extent -1.43,-1.52 1.43,0.85, body extent -1,-0.8 1,0.8, height 0.7
IEC_HotSurface_Small [mil]
  silkscreen extent -107,-93 107,92
SOD-128 [mm] "SMD, 2-Leads, Body 4x2.7mm, Height 1.1mm"
  rect 1.4x2.1 smd paste-0.1: 1(-2.2,0) 2(2.2,0)
  silkscreen extent -3.45,-1.45 2.95,1.45, body extent -2.5,-1.35 2.5,1.35, height 1.11
SSOP-16 [mm] "SSOP, 16-Leads, Body 4.9x3.91mm, Pitch 0.635mm"
  rrect22% 1.45x0.45 smd: 1(-2.725,2.222) 2(-2.725,1.588) 3(-2.725,0.953) 4(-2.725,0.318) 5(-2.725,-0.317) 6(-2.725,-0.952) 7(-2.725,-1.587) 8(-2.725,-2.222) 9(2.725,-2.222) 10(2.725,-1.588) 11(2.725,-0.953) 12(2.725,-0.318) 13(2.725,0.317) 14(2.725,0.952) 15(2.725,1.587) 16(2.725,2.222)
  silkscreen extent -1.6,-2.5 1.6,2.8, body extent -2.99,-2.5 3,2.5, height 1.75
Sullins_GRPB122VWVN [mm] "Header, 1.27mm, 12x2, TH"
  rect 1x1 hole 0.7: 1(-0.635,6.985)
  round 1 hole 0.7: 2(0.635,6.985) 3(-0.635,5.715) 4(0.635,5.715) 5(-0.635,4.445) 6(0.635,4.445) 7(-0.635,3.175) 8(0.635,3.175) 9(-0.635,1.905) 10(0.635,1.905) 11(-0.635,0.635) 12(0.635,0.635) 13(-0.635,-0.635) 14(0.635,-0.635) 15(-0.635,-1.905) 16(0.635,-1.905) 17(-0.635,-3.175) 18(0.635,-3.175) 19(-0.635,-4.445) 20(0.635,-4.445) 21(-0.635,-5.715) 22(0.635,-5.715) 23(-0.635,-6.985) 24(0.635,-6.985)
  silkscreen extent -2,-7.62 1.7,7.62, body extent -1.7,-7.62 1.7,7.62, height 4
TI_Symbol_Overlay_Small [mil]
  silkscreen extent -90,-88 91,88
TP_25MIL-SMT#1 [mil]
  round 25 smd far side mask-2.5: 1(0,0)
TP_25MIL-SMT#2 [mil]
  round 25 smd mask-2.5: 1(0,0)
USON-8L [mm] "SON, 8-Leads, Body 3x2mm, Pitch 0.5mm"
  rrect40% 0.6x0.25 smd: 1(-1.4,0.75) 2(-1.4,0.25) 3(-1.4,-0.25) 4(-1.4,-0.75) 5(1.4,-0.75) 6(1.4,-0.25) 7(1.4,0.25) 8(1.4,0.75)
  rrect50% 0.2x1.6 smd: 9(0,0)
  silkscreen extent -1.55,-1.17 0.65,1.17, body extent -1.55,-1.05 1.55,1.05, height 0.6
WEEE_Minimum [mil] "WEEElie bin"
  silkscreen extent -95,-172 99,104

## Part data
C1 C4 C7: library part CMP-0006272-2, "CAP, CERM, 1 uF, 10 V, +/- 10%, X6S, 0402", Cap_Case=0402, Manufacturer=TDK, Supplier Part Number 1=445-4978-1-ND, TempCo=X5R, Tolerance_%=10%, Value1=Unknown, Value2=16V, ValueDisplayed=1uF
C2 C19: library part CMP-0006408-2, "CAP, CERM, 10 pF, 50 V, +/- 5%, C0G/NP0, 0402", Cap_Case=0402, Manufacturer=MuRata, Supplier Part Number 1=81-GRM1555C1H100JA1D, TempCo=C0G/NP0, Tolerance_%=5%, Value1=Unknown, Value2=50V, ValueDisplayed=10pF
C3 C8 C10: library part CMP-0006356-2, "CAP, CERM, 0.1 uF, 50 V, +/- 10%, X7R, AEC-Q200 Grade 1, 0402", Cap_Case=0402, Manufacturer=MuRata, Supplier Part Number 1=490-10672-1-ND, TempCo=X7R, Tolerance_%=10%, Value1=Unknown, Value2=50V, ValueDisplayed=0.1uF
C5 C9 C14 C17 C20: library part CMP-0097887-1, "Chip Multilayer Ceramic Capacitors for General Purpose, 0402, 2.2uF, X5R, 15%, 20%, 10V", Manufacturer=Murata, Operating Temperature Range="-55°C to +85°C", TempCo=15%, Temperature Characteristic=X5R, Tolerance_%=20%, ValueDisplayed=2.2uF
C6: library part CMP-0006298-2, "CAP, CERM, 0.047 uF, 50 V, +/- 10%, X7R, 0402", Cap_Case=0402, Manufacturer=TDK, Supplier Part Number 1=445-7336-1-ND, TempCo=X7R, Tolerance_%=10%, Value1="0.06407 ohm", Value2=50V, ValueDisplayed=0.047uF
C11 C16: library part CMP-0078699-1, "CAP, CERM, 47 µF, 10 V,+/- 20%, X5R, 0805", Cap_Case=0805, Manufacturer=MuRata, Supplier Part Number 1=490-9961-1-ND, TempCo=X5R, Tolerance_%=20%, Value2=10V, ValueDisplayed=47µF
C13: library part CMP-0006648-2, "CAP, CERM, 0.22 uF, 16 V, +/- 10%, X7R, 0402", Cap_Case=0402, Manufacturer=MuRata, Supplier Part Number 1=490-5418-1-ND, TempCo=X7R, Tolerance_%=10%, Value1=Unknown, Value2=16V, ValueDisplayed=0.22uF
C15 C21 C23 C25 C26 C44 C49 C50 C56 C72 C128 C129: library part CMP-0007497-5, "CAP, CERM, 10 uF, 10 V, +/- 20%, X7R, 0603", Cap_Case=0603, Manufacturer=MuRata, Supplier Part Number 1=81-GRM188Z71A106MA3D, TempCo=X7R, Tolerance_%=20%, Value1=Unknown, Value2=10V, ValueDisplayed=10uF
C18 C22 C35: library part CMP-0064947-2, "CAP, CERM, 1 uF, 6.3 V,+/- 10%, X7R, 0402", Cap_Case=0402, Manufacturer=MuRata, Supplier Part Number 1=490-10024-1-ND, TempCo=X7R, Tolerance_%=10%, Value1=Unknown, Value2=6.3V, ValueDisplayed=1uF
C27: library part CMP-0094778-1, "Multilayer Ceramic Capacitors MLCC - SMD/SMT 0805 4.7uF 10%, 16VDC,  X7R 15%", Manufacturer=Murata, Operating Temperature Range="-55°C to +125°C", TempCo=15%, Temperature Characteristic=X7R, Tolerance_%=10%, ValueDisplayed=4.7uF
C28 C60 C73: library part CMP-0007398-4, "CAP, CERM, 0.47 uF, 16 V, +/- 10%, X7R, 0603", Cap_Case=0603, Manufacturer=MuRata, Supplier Part Number 1=490-3295-1-ND, TempCo=X7R, Tolerance_%=10%, Value1=Unknown, Value2=16V, ValueDisplayed=0.47uF
C29: library part CMP-0078265-1, "CAP, CERM, 0.22 µF, 16 V,+/- 10%, X7R, AEC-Q200 Grade 1, 0402", Cap_Case=0402, Manufacturer=MuRata, Supplier Part Number 1=490-10671-1-ND, TempCo=X7R, Tolerance_%=10%, Value2=16V, ValueDisplayed=0.22µF
C30: library part CMP-0064967-2, "CAP, CERM, 0.47 uF, 10 V,+/- 10%, X7S, 0402", Cap_Case=0402, Manufacturer=MuRata, Supplier Part Number 1=490-14427-1-ND, TempCo=X7S, Tolerance_%=10%, Value1=Unknown, Value2=10V, ValueDisplayed=0.47uF
C31: library part CMP-0007497-5, "CAP, CERM, 10 uF, 10 V, +/- 10%, X5R, 0603", Cap_Case=0603, Manufacturer=MuRata, Supplier Part Number 1=81-GRM188Z71A106MA3D, TempCo=X7R, Tolerance_%=20%, Value1=Unknown, Value2=10V, ValueDisplayed=10uF
C32: library part CMP-0006564-3, "CAP, CERM, 10 uF, 10 V, +/- 20%, X5R, 0402", Cap_Case=0402, Manufacturer=MuRata, TempCo=X5R, Tolerance_%=20%, Value1=Unknown, Value2=10V, ValueDisplayed=10uF
C33: library part CMP-0008944-2, "CAP, CERM, 47 uF, 10 V, +/- 10%, X5R, 1206", Cap_Case=1206, Manufacturer=MuRata, Supplier Part Number 1=81-GRM31CR61A476KE5L, TempCo=X5R, Tolerance_%=10%, Value1=Unknown, Value2=10V, ValueDisplayed=47uF
C34: library part CMP-0064969-1, "CAP, CERM, 0.1 uF, 10 V,+/- 10%, X7S, 0201", Cap_Case=0201, Manufacturer=MuRata, Supplier Part Number 1=490-14450-1-ND, TempCo=X7S, Tolerance_%=10%, Value1=Unknown, Value2=10V, ValueDisplayed=0.1uF
C36: library part CMP-0078623-1, "CAP, CERM, 10 µF, 10 V,+/- 20%, X5R, 0402", Cap_Case=0402_080, Manufacturer=AVX, Supplier Part Number 1=478-10052-1-ND, TempCo=X5R, Tolerance_%=20%, Value2=10V, ValueDisplayed=10µF
C37 C39 C40: library part CMP-0009717-2, "CAP, CERM, 0.1 uF, 16 V, +/- 10%, X5R, 0201", Cap_Case=0201, Manufacturer=MuRata, Supplier Part Number 1=490-9985-1-ND, TempCo=X5R, Tolerance_%=10%, Value1=Unknown, Value2=16V, ValueDisplayed=0.1uF
C38: library part CMP-0009720-2, "CAP, CERM, 0.01 uF, 6.3 V, +/- 10%, X7R, 0201", Cap_Case=0201, Manufacturer=MuRata, Supplier Part Number 1=490-1262-1-ND, TempCo=X7R, Tolerance_%=10%, Value1=Unknown, Value2=6.3V, ValueDisplayed=0.01uF
C41 C42: library part CMP-0124498-1, "Ceramic Capacitor for Automotive 22pF  ±5% 25VDC C0G 0201 Paper T/R", Manufacturer=Murata, Operating Temperature Range="-55°C to +125°C", TempCo=30ppm/°C, Temperature Characteristic=C0G, Tolerance_%=0.05%, ValueDisplayed=22pF
C43: library part CMP-0064946-2, "CAP, CERM, 0.1 uF, 50 V,+/- 10%, X7R, 0402", Cap_Case=0402, Manufacturer=TDK, Supplier Part Number 1=445-173610-1-ND, TempCo=X7R, Tolerance_%=10%, Value1=Unknown, Value2=50V, ValueDisplayed=0.1uF
C45 C69 C74: library part CMP-0006470-2, "CAP, CERM, 470 pF, 50 V, +/- 5%, C0G/NP0, 0402", Cap_Case=0402, Manufacturer=MuRata, Supplier Part Number 1=490-1297-1-ND, TempCo=C0G/NP0, Tolerance_%=5%, Value1=Unknown, Value2=50V, ValueDisplayed=470pF
C46 C47: library part CMP-0006367-2, "CAP, CERM, 4.7 pF, 50 V, +/- 2%, C0G/NP0, 0402", Cap_Case=0402, Manufacturer=MuRata, Supplier Part Number 1=490-8102-1-ND, TempCo=C0G/NP0, Tolerance_%=2%, Value1=Unknown, Value2=50V, ValueDisplayed=4.7pF
C48: library part CMP-0860563-1, "CAP, CERM, 0.22 µF, 16 V,+/- 10%, X7R, 0402", Cap_Case=0402, Manufacturer="Samsung Electro-Mechanics", TempCo=X7R, Tolerance_%=10%, Value2=16V, ValueDisplayed=0.22µF
"CAUTION HOT SURFACE1": library part CMP-0074837-2, "IEC 61010-1 Hot Surface Warning", Manufacturer="Texas Instruments"
D1: library part CMP-0078758-2, "Diode, Schottky, 30 V, 2 A, AEC-Q101, SOD-128", Manufacturer=Nexperia, Value1=2A, Value2=0.36V
D2 D3: library part CMP-0090807-1, "LED Uni-Color Yellow 588nm 2-Pin Chip 0402(1006Metric) T/R", Color=Yellow, Digikey Part Number=VLMY1500-GS08CT-ND, Forward Current=20mA, Manufacturer=Vishay, Mouser Part Number=78-VLMY1500-GS08, Operating Temperature Range="-30°C to +85 °C", Power_TotalModule=75mW
FID1 FID2 FID3 FID4 FID5 FID6: library part CMP-0077181-1, "Fiducial mark.  There is nothing to buy or mount.", Manufacturer=N/A
J1: library part CMP-0054595-1, "Header, 1.27mm, 12x2, Gold, TH", Current_A=1A, Manufacturer="Sullins Connector Solutions", Supplier Part Number 1=S9015E-12-ND
J2: library part CMP-0055293-1, "Connector, Receptacle, Micro-USB Type B, R/A, Bottom Mount SMT", Manufacturer=Molex, Supplier Part Number 1=WM1399CT-ND
J3 J4 J5 J6 J7 J8 J9 J10 J11 J12 J13 J14 J15 J17 J19 J21 J22 J24 J25 J26 J27 J28 J29 J30 J31 J32: library part CMP-0124126-3, Manufacturer=Altium, Operating Temperature Range=to
L1: library part CMP-0078934-1, "Inductor, Ferrite Bead, Ferrite, 2.2 A, 0.035 ohm, AEC-Q200 Grade 1, SMD", Manufacturer=MuRata, Supplier Part Number 1=490-16506-1-ND, Value1="0.035 ohm", Value2=2.2A
L2 L15: library part CMP-0092096-1, "470nH Shielded Wirewound Inductor 3A 42mOhm Max 0805 (2012 Metric)", Digikey Part Number=490-17727-1-ND, Manufacturer=Murata, Mouser Part Number=81-DFE201210U-R47MP2, Operating Temperature Range="-40°C to +125°C", Part Number=DFE201210U-R47M{}P2, Test Frequency=1MHz, Tolerance_%=20%
L3 L6: library part CMP-0124620-1, "100 nH Shielded Drum Core, Wirewound Inductor 3.65 A 22mOhm Max 0806 (2016 Metric)", Digikey Part Number=3442-SPH201610UR10MTTR-ND, Manufacturer=Sunlord, Operating Temperature Range="-40°C to +125°C", Self Resonant Frequency=583MHz, Test Frequency=1MHz, Tolerance_%=20%
L4 L7: library part CMP-0077879-2, "Ferrite Bead, 120 ohm @ 100 MHz, 1.9 A, 0603", Manufacturer=MuRata, Supplier Part Number 1=490-13261-1-ND, Value1="0.04 ohm", Value2=1.9A, ValueDisplayed="120 ohm"
Logo1: library part CMP-0074838-1, "Texas Instrument Corporate Signature"
Logo2: library part CMP-0074844-2, Manufacturer="Texas Instruments"
Logo4: library part CMP-0074769-1
Q1 Q2: library part CMP-0091833-1, "N-Channel 20V 250mA (Ta) 500mW (Ta) Surface Mount VESM", Digikey Part Number=SSM3K35AMFVL3FCT-ND, Drain To Source Breakdown Voltage=20V, Input Capacitace At Vds="18pF @ 10V", Manufacturer=Toshiba, Mouser Part Number=757-SSM3K35AMFVL3F, Operating Temperature Range="to +150°C", Power_W=150mW, Pulse Drain Current=600mA, Typ Forward Diode Voltage=0.8V
R1 R3 R5 R7 R12 R13 R17 R18: library part CMP-0093147-1, "Res Jumper Thick Film 0402 0 Ohm 5% 1/16W Molded SMD Paper T/R", Digikey Part Number=YAG1279CT-ND, Manufacturer=Yageo, Mouser Part Number=603-RC0402JR-070RP, Operating Temperature Range="-55°C to +155°C", Power_W=63mW
R2: library part CMP-0026367-2, "RES, 40.2 k, 1%, 0.063 W, AEC-Q200 Grade 0, 0402", Manufacturer=Vishay-Dale, Power_W=63mW, Supplier Part Number 1=541-40.2KLCT-ND, TempCo="100 ppm/C", Tolerance_%=1%, Value2=0.063W, Value_Code=40k2, ValueDisplayed=40.2k
R4 R24 R25 R44 R49 R73 R74 R75: library part CMP-0026245-2, "RES, 2.00 M, 1%, 0.063 W, AEC-Q200 Grade 0, 0402", Manufacturer=Vishay-Dale, Power_W=63mW, Supplier Part Number 1=541-2.00MLCT-ND, TempCo="100 ppm/C", Tolerance_%=1%, Value2=0.063W, Value_Code=2M00, ValueDisplayed=2.00M
R6 R11: library part CMP-0089143-1, "0 Ohms Jumper 0.1W, 1/10W Chip Resistor 0603 (1608 Metric) Automotive AEC-Q200 Thick Film", Digikey Part Number=P0.0GCT-ND, Manufacturer=Panasonic, Mouser Part Number=667-ERJ-3GEY0R00V, Operating Temperature Range="-55°C to +155°C", Power_W=100mW, TempCo=-100/+600ppm/°C, Tolerance_%=5%
R8 R9 R16 R20: library part CMP-0025958-3, "RES, 10.0 k, 1%, 0.063 W, AEC-Q200 Grade 0, 0402", Manufacturer=Vishay-Dale, Power_W=63mW, Supplier Part Number 1=541-10.0KLCT-ND, TempCo="100 ppm/C", Tolerance_%=1%, Value2=0.063W, Value_Code=10k0, ValueDisplayed=10.0k
R10: library part CMP-0025950-3, "RES, 100 k, 1%, 0.063 W, AEC-Q200 Grade 0, 0402", Manufacturer=Vishay-Dale, Power_W=63mW, Supplier Part Number 1=541-100KLCT-ND, TempCo="100 ppm/C", Tolerance_%=1%, Value2=0.063W, Value_Code=100k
